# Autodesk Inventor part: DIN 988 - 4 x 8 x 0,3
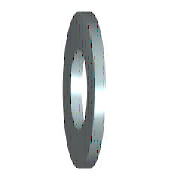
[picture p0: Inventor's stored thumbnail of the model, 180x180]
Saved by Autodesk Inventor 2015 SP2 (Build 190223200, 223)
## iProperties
Created: 2014-02
Part Number: DIN 988 - 4 x 8 x 0,3
Material: Stahl, weich
Description: Paßscheibe
Document SubType Name: Modeling
Standard: DIN 988
Designer: rYan
Standard Revision: 1990
Standards Organization: DIN
Language: de-DE
Size Designation: 4 x 8 x 0,3
Categories: <MemberInstance><Categories><Category DisplayName="Wellenteile" InternalName="7f7aeb1f-a693-4053-b835-cee3144e0d98" Mnemonic="SHFT"><Category DisplayName="Unter
Density: 7.85 g/cm^3
Appearance: Halbpoliert
IsCustomPart: 0
Author: rYan
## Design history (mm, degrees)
sketch "Skizze1"
  geometry: L1 (-21, 0)-(21, 0) reference; L2 (0, 21)-(0, -21) reference; C1 r 2 at (0, 0); C2 r 4 at (0, 0)
  constraints: 2 centre point, 2 midpoint, 1 coincident, 1 other
  dimensions: "d0" = 4 diameter of C1 (= SD1); "d1" = 8 diameter of C2 (= SD2)
extrude "Körper" new body sketch "Skizze1" distance "d2" = 0.3 (= SD); taper "d3" = 0 deg
body "Solid1"
other parameters: "SD2" = 8 [user parameter; used in 1 equation term], "SD" = 0.3 [user parameter; used in 1 equation term], "SD1" = 4 [user parameter; used in 1 equation term], "d4" = 0, "d5" = 0, "NND" = 4 [user parameter], "SR" = 4 (= 0.5 x NND2) [user parameter], "NND2" = 8 [user parameter; used in 1 equation term]
